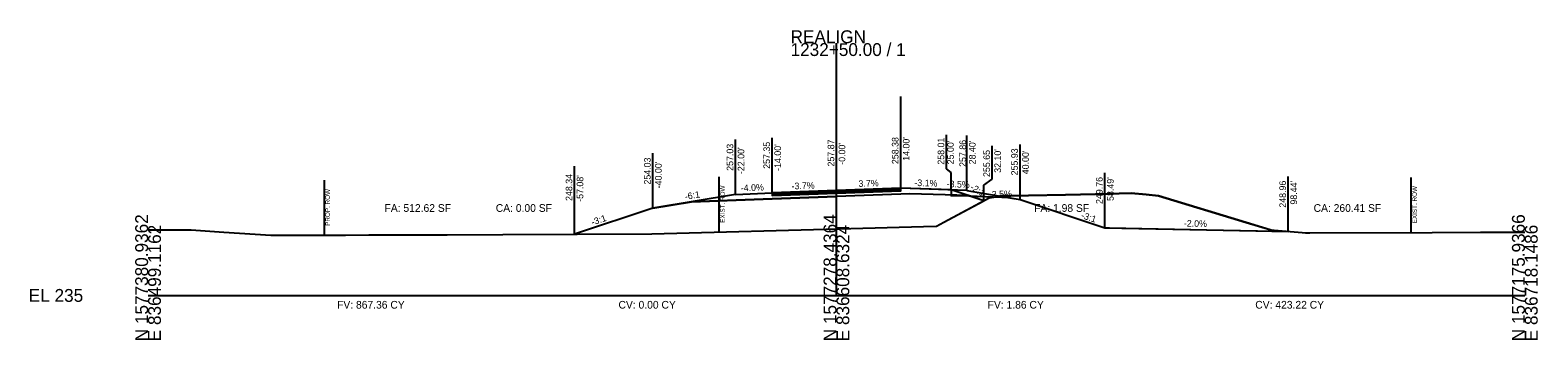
# Model space of a CAD drawing. Extents: x -26 to 6303, y -16 to 9563.
# Drawn here: x 974.3 to 1302.8, y 1490.3 to 1557.8 of the extents above; entities that cross this region are included whole.
import ezdxf

# ---------------------------------------------------------------- set-up
doc = ezdxf.new("R2010")
doc.units = 0
for name, color, linetype in [('ASPHALT_19MM1', 7, 'Continuous'), ('ASPHALT_9_5MM1', 7, 'Continuous'), ('CONST_DCH', 7, 'Continuous'), ('CONST_LV3', 7, 'Continuous'), ('Draft_XS_Grid', 7, 'Continuous'), ('DTM_TEMP_DROP', 7, 'Continuous'), ('DTM_X_GROUND', 7, 'Continuous'), ('X_PROFILES_1', 7, 'Continuous'), ('X_TRANS_EOP', 7, 'Continuous'), ('XS_CELL', 7, 'Continuous'), ('XS_M_SHAPES_EARTHWORK', 7, 'Continuous'), ('XS_P_ASPHALT', 7, 'Continuous'), ('XS_P_DR_ASPHALT', 7, 'Continuous'), ('XS_P_GROUND', 7, 'Continuous'), ('XS_P_ROW', 7, 'Continuous'), ('XS_P_SHOULDER', 7, 'Continuous'), ('XS_P_SUBGRADE_GRANULAR', 7, 'Continuous'), ('XS_P_TX_CLEARZONE', 7, 'Continuous'), ('XS_P_TX_FS_BS', 7, 'Continuous'), ('XS_PLAN_CLEAR_ZONE', 7, 'Continuous'), ('XS_SHEET_EW_TX_AREA', 7, 'Continuous'), ('XS_SHEET_EW_TX_VOLUME', 7, 'Continuous'), ('XS_X_ROW', 7, 'Continuous')]:
    doc.layers.add(name, color=color, linetype=linetype)

msp = doc.modelspace()

# ---------------------------------------------------------------- linework, layer by layer
at = {"layer": 'ASPHALT_19MM1'}
msp.add_lwpolyline([(1136, 1522.02), (1136, 1521.75), (1150, 1522.26), (1150, 1522.26), (1164, 1522.78), (1164, 1522.78), (1164, 1523.05), (1164, 1523.05), (1164, 1523.05), (1150, 1522.53), (1150, 1522.53), (1136, 1522.02), (1136, 1522.02)], dxfattribs=at)
at = {"layer": 'ASPHALT_9_5MM1'}
msp.add_lwpolyline([(1136, 1522.35), (1136, 1522.23), (1150, 1522.74), (1150, 1522.74), (1164, 1523.25), (1164, 1523.25), (1164, 1523.38), (1164, 1523.38), (1164, 1523.38), (1150, 1522.87), (1150, 1522.87), (1136, 1522.35), (1136, 1522.35)], dxfattribs=at)
at = {"layer": 'CONST_LV3'}
for points in [[(1164, 1523.36), (1164, 1523.36), (1150, 1522.87)], [(1178.4, 1522.86), (1178.4, 1522.86), (1164, 1523.36)], [(1110, 1519.03), (1118.44, 1520.44), (1118.44, 1520.44)]]:
    msp.add_lwpolyline(points, dxfattribs=at)
at = {"layer": 'DTM_X_GROUND'}
msp.add_lwpolyline([(1000, 1514.3), (1009.36, 1514.28), (1016.53, 1513.82), (1026.72, 1513.15), (1033.78, 1513.16), (1042.99, 1513.17), (1048.13, 1513.18), (1065.17, 1513.23), (1077.34, 1513.26), (1109.8, 1513.43), (1153.12, 1514.61), (1168.95, 1515.03), (1171.77, 1515.11), (1173.39, 1515.97), (1183.29, 1521.28), (1184.31, 1521.45), (1185.82, 1521.7), (1191.86, 1521.82), (1199.93, 1521.96), (1206.47, 1522.11), (1214.23, 1522.28), (1217.46, 1521.97), (1220.21, 1521.73), (1239.29, 1515.92), (1244.63, 1514.27), (1245.35, 1514.22), (1251.45, 1513.71), (1252.2, 1513.65), (1252.45, 1513.63), (1253.16, 1513.63), (1279.79, 1513.75), (1290.31, 1513.8), (1300, 1513.81)], dxfattribs=at)
at = {"layer": 'X_TRANS_EOP'}
msp.add_line((1164, 1523.36), (1164, 1543.36), dxfattribs=at)
at = {"layer": 'XS_CELL'}
for p, q in [((1150, 1500), (1150, 1555)), ((1000, 1500), (1150, 1500)), ((1150, 1500), (1300, 1500))]:
    msp.add_line(p, q, dxfattribs=at)
at = {"layer": 'XS_M_SHAPES_EARTHWORK'}
msp.add_lwpolyline([(1092.92, 1513.34), (1109.8, 1513.43), (1153.12, 1514.61), (1168.95, 1515.03), (1171.77, 1515.11), (1173.39, 1515.97), (1182.1, 1520.65), (1178.77, 1521.76), (1166, 1522.18), (1164, 1522.11), (1150, 1521.6), (1136, 1521.08), (1134, 1521.01), (1118.44, 1520.44), (1110, 1519.03)], close=True, dxfattribs=at)
at = {"layer": 'XS_P_GROUND'}
for points in [[(1128, 1522.03), (1110, 1519.03), (1092.92, 1513.34)], [(1182.1, 1520.65), (1182.1, 1520.65), (1175, 1523.01)], [(1178.4, 1522.86), (1190, 1520.93), (1208.49, 1514.76)], [(1208.49, 1514.76), (1209.49, 1514.74)], [(1209.49, 1514.74), (1248.44, 1513.96)]]:
    msp.add_lwpolyline(points, dxfattribs=at)
at = {"layer": 'XS_P_ROW'}
msp.add_line((1038.43, 1513.16), (1038.43, 1525.16), dxfattribs=at)
at = {"layer": 'XS_P_SHOULDER'}
for points in [[(1128, 1522.03), (1136, 1522.35), (1136, 1522.35)], [(1175, 1523.01), (1175, 1523.01), (1164, 1523.38)], [(1178.4, 1522.86), (1178.4, 1522.86), (1175, 1522.98)]]:
    msp.add_lwpolyline(points, dxfattribs=at)
at = {"layer": 'XS_P_SUBGRADE_GRANULAR'}
for points in [[(1136, 1521.08), (1150, 1521.6), (1150, 1521.6)], [(1164, 1522.11), (1164, 1522.11), (1150, 1521.6)], [(1178.77, 1521.76), (1178.77, 1521.76), (1166, 1522.18), (1166, 1522.18), (1164, 1522.11)], [(1175, 1522.98), (1175, 1521.71)], [(1187.88, 1521.28), (1187.88, 1521.28), (1177, 1521.71), (1175, 1521.71), (1175, 1521.71)], [(1118.44, 1520.44), (1134, 1521.01), (1134, 1521.01), (1136, 1521.08), (1136, 1521.08)]]:
    msp.add_lwpolyline(points, dxfattribs=at)
at = {"layer": 'XS_P_TX_CLEARZONE'}
for p, q in [((1136, 1522.35), (1136, 1534.35)), ((1150, 1522.87), (1150, 1534.87)), ((1164, 1523.38), (1164, 1535.38)), ((1173.97, 1527.63), (1173.97, 1534.98)), ((1178.4, 1522.86), (1178.4, 1534.86)), ((1110, 1519.03), (1110, 1531.03)), ((1128, 1522.03), (1128, 1534.03)), ((1183.93, 1525.34), (1183.93, 1532.65)), ((1190, 1520.93), (1190, 1532.93)), ((1092.92, 1513.34), (1092.92, 1528.21)), ((1175, 1526.83), (1173.97, 1527.63)), ((1175, 1522.98), (1175, 1526.83)), ((1182.1, 1524.01), (1183.93, 1525.34)), ((1208.49, 1514.76), (1208.49, 1526.76)), ((1248.44, 1513.96), (1248.44, 1525.96)), ((1182.1, 1520.65), (1182.1, 1524.01))]:
    msp.add_line(p, q, dxfattribs=at)
at = {"layer": 'XS_P_TX_FS_BS'}
for p, q in [((1190, 1520.93), (1208.49, 1514.76)), ((1208.49, 1514.76), (1245.42, 1514.02))]:
    msp.add_line(p, q, dxfattribs=at)
for points in [[(1245.42, 1514.02), (1239.29, 1515.92), (1220.21, 1521.73), (1217.46, 1521.97), (1214.23, 1522.28), (1206.47, 1522.11), (1199.93, 1521.96), (1191.86, 1521.82), (1185.82, 1521.7), (1185.57, 1521.66)], [(1185.57, 1521.66), (1187.76, 1521.3), (1190, 1520.93)]]:
    msp.add_lwpolyline(points, dxfattribs=at)
at = {"layer": 'XS_PLAN_CLEAR_ZONE'}
msp.add_lwpolyline([(1136, 1522.23), (1136, 1522.02), (1150, 1522.53), (1150, 1522.53), (1164, 1523.05), (1164, 1523.05), (1164, 1523.25), (1164, 1523.25), (1164, 1523.25), (1150, 1522.74), (1150, 1522.74), (1136, 1522.23), (1136, 1522.23)], dxfattribs=at)
at = {"layer": 'XS_X_ROW'}
for p, q in [((1124.46, 1513.83), (1124.46, 1525.83)), ((1275.27, 1513.73), (1275.27, 1525.73))]:
    msp.add_line(p, q, dxfattribs=at)

# ---------------------------------------------------------------- texts
at = {"layer": 'CONST_DCH'}
for p in [(1135.92, 1522.23), (1149.92, 1522.75), (1163.92, 1523.26)]:
    msp.add_text('X', height=0.24, dxfattribs=at).set_placement(p)
at = {"layer": 'Draft_XS_Grid'}
msp.add_text('-', height=0.0001, dxfattribs=at).set_placement((1000, 1500))
at = {"layer": 'DTM_TEMP_DROP'}
for p in [(1174.92, 1522.86), (1182.02, 1520.53), (1092.84, 1513.22)]:
    msp.add_text('X', height=0.24, dxfattribs=at).set_placement(p)
at = {"layer": 'X_PROFILES_1'}
for p in [(1178.33, 1522.74), (1189.92, 1520.81)]:
    msp.add_text('X', height=0.24, dxfattribs=at).set_placement(p)
at = {"layer": 'XS_CELL'}
for s, p in [('REALIGN', (1140, 1555)), ('1232+50.00 / 1', (1140, 1552.2)), ('EL 235', (974, 1498.6))]:
    msp.add_text(s, height=2.8, dxfattribs=at).set_placement(p)
for s, p in [('N 1577380.9362', (1000, 1490)), ('E 836499.1162', (1002.8, 1490)), ('N 1577278.4364', (1150, 1490)), ('E 836608.6324', (1152.8, 1490)), ('N 1577175.9366', (1300, 1490)), ('E 836718.1486', (1302.8, 1490))]:
    msp.add_text(s, height=2.8, rotation=90, dxfattribs=at).set_placement(p)
at = {"layer": 'XS_P_ASPHALT'}
msp.add_text('X', height=0.24, dxfattribs=at).set_placement((1208.41, 1514.64))
at = {"layer": 'XS_P_DR_ASPHALT'}
msp.add_text('X', height=0.24, dxfattribs=at).set_placement((1109.92, 1518.91))
at = {"layer": 'XS_P_ROW'}
msp.add_text('PROP. ROW', height=1, rotation=90, dxfattribs=at).set_placement((1039.63, 1515.16))
at = {"layer": 'XS_P_SHOULDER'}
for p in [(1127.92, 1521.91), (1174.92, 1522.89)]:
    msp.add_text('X', height=0.24, dxfattribs=at).set_placement(p)
at = {"layer": 'XS_P_SUBGRADE_GRANULAR'}
for p in [(1182.02, 1520.53), (1092.84, 1513.22), (1248.37, 1513.84)]:
    msp.add_text('X', height=0.24, dxfattribs=at).set_placement(p)
at = {"layer": 'XS_P_TX_CLEARZONE'}
for s, p in [('258.38', (1163.52, 1528.63)), ("14.00'", (1165.92, 1529.35)), ('258.01', (1173.49, 1528.51)), ('257.03', (1127.52, 1527.17)), ("-22.00'", (1129.92, 1526.46)), ('257.35', (1135.52, 1527.6)), ("-14.00'", (1137.92, 1527.15)), ('257.87', (1149.52, 1528.11)), ("-0.00'", (1151.92, 1528.48)), ("25.00'", (1175.58, 1528.58)), ('257.86', (1178.24, 1528.02)), ("28.40'", (1180.32, 1528.58)), ('255.65', (1183.45, 1525.82)), ("32.10'", (1185.85, 1526.73)), ('255.93', (1189.52, 1526.17)), ("40.00'", (1191.92, 1526.42)), ('254.03', (1109.52, 1524.17)), ("-40.00'", (1111.92, 1523.35)), ('248.34', (1092.44, 1520.6)), ("-57.08'", (1094.84, 1520.41)), ('249.76', (1208.01, 1519.93)), ("58.49'", (1210.41, 1520.6)), ('248.96', (1247.96, 1519.13)), ("98.44'", (1250.36, 1519.8))]:
    msp.add_text(s, height=1.44, rotation=90, dxfattribs=at).set_placement(p)
at = {"layer": 'XS_P_TX_FS_BS'}
for s, rotation, p in [('-3.7%', 2.0984, (1140.24, 1523.11)), ('3.7%', 2.099, (1154.83, 1523.64)), ('-3.1%', 358.1964, (1166.96, 1523.87)), ('-3.5%', 358.0064, (1173.99, 1523.61)), ('-6:1', 9.4642, (1117.08, 1520.82)), ('-4.0%', 2.2906, (1129.18, 1522.68)), ('-2:1', 329.1133, (1179, 1523.2)), ('3.5%', 2.0284, (1183.88, 1521.31)), ('-3:1', 341.5651, (1203.2, 1516.89)), ('-3:1', 18.4332, (1096.85, 1515.23)), ('-2.0%', 358.8542, (1225.69, 1515.02))]:
    msp.add_text(s, height=1.44, rotation=rotation, dxfattribs=at).set_placement(p)
at = {"layer": 'XS_SHEET_EW_TX_AREA'}
for s, p in [('FA: 512.62 SF', (1051.53, 1518.22)), ('CA: 0.00 SF', (1075.77, 1518.22)), ('FA: 1.98 SF', (1193.08, 1518.22)), ('CA: 260.41 SF', (1253.98, 1518.22))]:
    msp.add_text(s, height=1.68, dxfattribs=at).set_placement(p)
at = {"layer": 'XS_SHEET_EW_TX_VOLUME'}
for s, p in [('FV: 867.36 CY', (1041.19, 1497.12)), ('CV: 0.00 CY', (1102.51, 1497.12)), ('FV: 1.86 CY', (1182.95, 1497.12)), ('CV: 423.22 CY', (1241.27, 1497.12))]:
    msp.add_text(s, height=1.68, dxfattribs=at).set_placement(p)
at = {"layer": 'XS_X_ROW'}
for p in [(1125.66, 1515.83), (1276.48, 1515.73)]:
    msp.add_text('EXIST. ROW', height=1, rotation=90, dxfattribs=at).set_placement(p)

doc.saveas('drawing.dxf')
